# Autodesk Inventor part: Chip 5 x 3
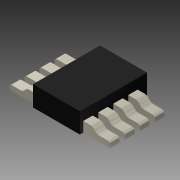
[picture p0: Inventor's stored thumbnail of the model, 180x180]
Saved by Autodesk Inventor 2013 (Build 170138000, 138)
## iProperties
Company: Autodesk Inc.
Created: 2005-12
Part Number: Chip 5 x 3
Document SubType Name: Modeling
Designer: Autodesk Inc.
Density: 1 g/cm^3
Mass: 0.0323479 g
Surface Area: 0.985249 cm^2
Volume: 0.0323479 cm^3
Material: Allgemein
Title: Personal Computer
Author: Autodesk Inc.
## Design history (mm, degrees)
sketch "Sketch1"
  geometry: L1 (0, 3.5)-(0, -3.5) reference; L2 (-2.45, 0)-(2.45, 0) reference; L3 (-1.75, 2.5)-(1.75, 2.5); L4 (1.75, 2.5)-(1.75, -2.5); L5 (1.75, -2.5)-(-1.75, -2.5); L6 (-1.75, -2.5)-(-1.75, 2.5)
  constraints: 8 end point, 2 parallel, 1 horizontal, 1 perpendicular, 2 other
  dimensions: "d0" = 3.5 distance of L3.start L3.end; "d1" = 5 distance of L5.end L3.start
extrude "Extrusion1" new body sketch "Sketch1" distance "d2" = 1.5; taper "d3" = 0 deg
workplane "Work Plane1"
sketch "Sketch2"
  geometry: L1 (0, 0)-(0, 1.5) reference; L2 (0, 1.5)-(3.5, 1.5) reference; L3 (3.5, 1.5)-(3.5, 0) reference; L4 (3.5, 0)-(0, 0) reference; L5 (3.5, 0.75)-(4.016, 0.75); L6 (4.32, 0.61)-(4.38, 0.54); L7 (4.684, 0.4)-(5.3, 0.4); L8 (5.5, 0.2)-(5.5, 0); L9 (5.5, 0)-(3.5, 0); A1 r 0.4 centre (4.016, 0.35) between (4.32, 0.61) and (4.016, 0.75); A2 r 0.4 centre (4.684, 0.8) between (4.38, 0.54) and (4.684, 0.4); A3 r 0.2 centre (5.3, 0.2) between (5.5, 0.2) and (5.3, 0.4); 3 further points
  constraints: 18 end point, 6 point on circle, 6 point on line, 6 tangent, 3 centre point, 3 parallel, 2 horizontal, 2 vertical, 1 equal radius, 1 midpoint, 1 perpendicular, 4 other
  dimensions: "d5" = 0.7 distance of L5.start point (4.2, 0.75); "d6" = 2 distance of L8.end L3.end; "d7" = 0.4 distance of point (5.5, 0.4) L8.end; "d8" = 1 distance of point (4.5, 0.4) point (5.5, 0.4); "d9" = 0.4 radius of A1; "d10" = 0.2 radius of A3
extrude "Extrusion2" join sketch "Sketch2" distance "d11" = 0.7; taper "d12" = 0 deg
pattern_linear "Rectangular Pattern1" dims "d15" = 3.35
mirror "Mirror1"
body "Solid1"
other parameters: "d4" = -0.25
